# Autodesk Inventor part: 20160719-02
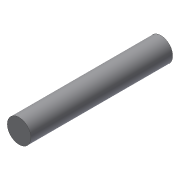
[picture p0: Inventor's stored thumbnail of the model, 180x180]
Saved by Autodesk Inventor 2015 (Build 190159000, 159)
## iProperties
Created: 2016-07
Part Number: 20160719-02
Material: Všeobecné
Document SubType Name: Modeling
Designer: navara
Mass: 0.589049 g
Surface Area: 5.10509 cm^2
Volume: 0.589049 cm^3
Density: 1 g/cm^3
Appearance: Výchozí
Author: navara
Mass: 0,6 g
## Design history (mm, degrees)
sketch "Náčrt1"
  geometry: C1 r 2.5 at (0, 0)
  constraints: 1 centre point
  dimensions: "d0" = 5 dimension on C1.centre C1; "d0" = 5 diameter of C1
extrude "Vysunutí1" new body sketch "Náčrt1" distance "d1" = 30; taper "d2" = 0 deg
node "Těleso1"
